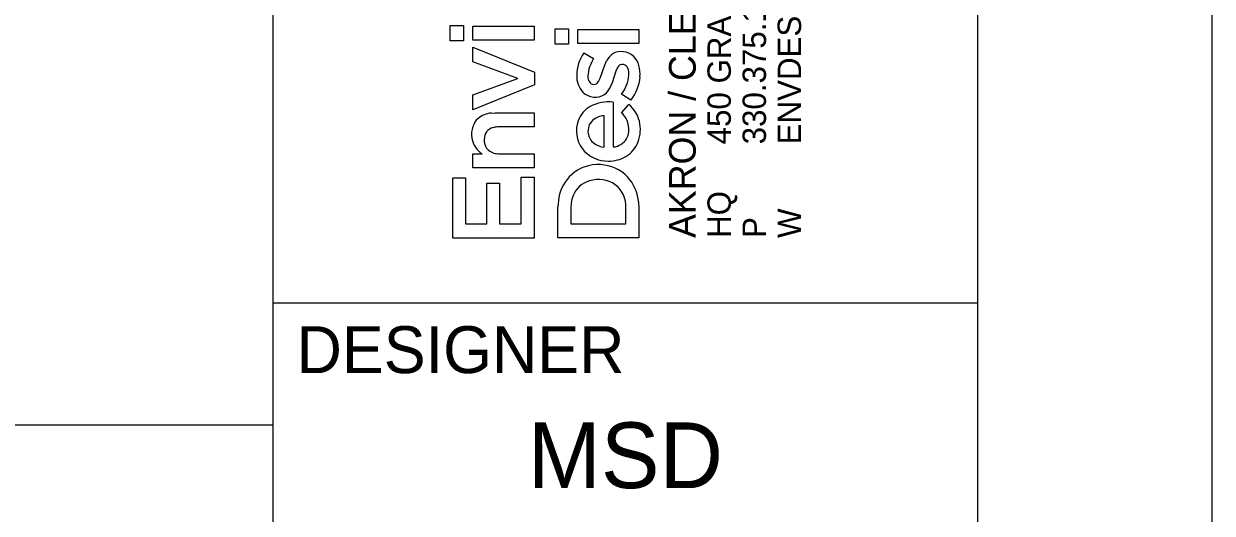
# Model space of a CAD drawing. Extents: x -4279 to 34, y -2047 to 22.
# Drawn here: x 31.469 to 34, y 2.552 to 3.594 of the extents above; entities that cross this region are included whole.
import ezdxf

# ---------------------------------------------------------------- set-up
doc = ezdxf.new("R2010")
doc.units = 0
for name, color, linetype in [('SH_Border', 7, 'Continuous'), ('SH_Cut_Line', 7, 'Continuous'), ('SH_Data', 7, 'Continuous'), ('SH_Text', 7, 'Continuous')]:
    doc.layers.add(name, color=color, linetype=linetype)

msp = doc.modelspace()

# ---------------------------------------------------------------- linework, layer by layer
at = {"layer": 'SH_Border'}
for p, q in [((32, 0.5), (32, 21.5)), ((32, 3), (33.5, 3))]:
    msp.add_line(p, q, dxfattribs=at)
msp.add_lwpolyline([(1.5, 21.5), (33.5, 21.5), (33.5, 0.5), (1.5, 0.5)], close=True, dxfattribs=at)
at = {"layer": 'SH_Cut_Line'}
msp.add_lwpolyline([(0, 0), (34, 0), (34, 22), (0, 22)], close=True, dxfattribs=at)
at = {"layer": 'SH_Data'}
for p, q in [((32.3771, 3.5582), (32.3771, 3.5903)), ((32.3771, 3.5903), (32.4054, 3.5903)), ((32.4054, 3.5903), (32.4054, 3.5582)), ((32.4254, 3.5594), (32.4254, 3.5893)), ((32.4254, 3.5893), (32.5557, 3.5893)), ((32.5557, 3.5893), (32.5557, 3.5594)), ((32.6005, 3.5511), (32.6005, 3.5832)), ((32.6005, 3.5832), (32.6289, 3.5832)), ((32.6289, 3.5832), (32.6289, 3.5511)), ((32.6489, 3.5523), (32.6489, 3.5822)), ((32.6489, 3.5822), (32.7792, 3.5822)), ((32.7792, 3.5822), (32.7792, 3.5523)), ((32.4054, 3.5582), (32.3771, 3.5582)), ((32.5557, 3.5594), (32.4254, 3.5594)), ((32.4254, 3.5133), (32.4254, 3.5446)), ((32.4254, 3.5446), (32.5567, 3.4913)), ((32.6289, 3.5511), (32.6005, 3.5511)), ((32.7792, 3.5523), (32.6489, 3.5523)), ((32.6615, 3.5321), (32.6827, 3.5203)), ((32.5212, 3.478), (32.4254, 3.5133)), ((32.6967, 3.4787), (32.7048, 3.5026)), ((32.7048, 3.5026), (32.7104, 3.5153)), ((32.7298, 3.4933), (32.7221, 3.4688)), ((32.7334, 3.501), (32.7298, 3.4933)), ((32.4254, 3.4429), (32.5212, 3.478)), ((32.5567, 3.4913), (32.5567, 3.4644)), ((32.693, 3.4712), (32.6967, 3.4787)), ((32.7221, 3.4688), (32.7182, 3.4592)), ((32.5567, 3.4644), (32.4254, 3.4109)), ((32.4254, 3.4109), (32.4254, 3.4429)), ((32.7621, 3.4314), (32.742, 3.4447)), ((32.7245, 3.4275), (32.7246, 3.3319)), ((32.7423, 3.4046), (32.7577, 3.422)), ((32.4644, 3.404), (32.4729, 3.4044)), ((32.4729, 3.4044), (32.5557, 3.4044)), ((32.5557, 3.4044), (32.5557, 3.3746)), ((32.7049, 3.3318), (32.7049, 3.3983)), ((32.5557, 3.3746), (32.4814, 3.3746)), ((32.4254, 3.2875), (32.4254, 3.3173)), ((32.4254, 3.3173), (32.4455, 3.3173)), ((32.4822, 3.3173), (32.5557, 3.3173)), ((32.5557, 3.3173), (32.5557, 3.2876)), ((32.7036, 3.3317), (32.7049, 3.3318)), ((32.383, 3.1379), (32.383, 3.266)), ((32.383, 3.266), (32.4101, 3.266)), ((32.4101, 3.266), (32.4101, 3.1683)), ((32.5557, 3.2876), (32.4254, 3.2875)), ((32.5286, 3.1683), (32.5286, 3.2672)), ((32.5286, 3.2672), (32.5557, 3.2672)), ((32.5557, 3.2672), (32.5557, 3.1379)), ((32.455, 3.1683), (32.455, 3.2549)), ((32.455, 3.2549), (32.4822, 3.2549)), ((32.4822, 3.2549), (32.4822, 3.1683)), ((32.7785, 3.215), (32.7792, 3.2021)), ((32.6064, 3.138), (32.6064, 3.204)), ((32.6347, 3.2118), (32.6341, 3.2023)), ((32.6341, 3.2023), (32.6341, 3.1684)), ((32.7515, 3.1683), (32.7515, 3.2024)), ((32.7792, 3.2021), (32.7792, 3.138)), ((32.4101, 3.1683), (32.455, 3.1683)), ((32.4822, 3.1683), (32.5286, 3.1683)), ((32.6341, 3.1684), (32.7515, 3.1683)), ((32.5557, 3.1379), (32.383, 3.1379)), ((32.7792, 3.138), (32.6064, 3.138))]:
    msp.add_line(p, q, dxfattribs=at)
for points in [[(32.3771, 3.5582), (32.3771, 3.5903), (32.4054, 3.5903), (32.4054, 3.5582)], [(32.4254, 3.5594), (32.4254, 3.5893), (32.5557, 3.5893), (32.5557, 3.5594)], [(32.6005, 3.5511), (32.6005, 3.5832), (32.6289, 3.5832), (32.6289, 3.5511)], [(32.6489, 3.5523), (32.6489, 3.5822), (32.7792, 3.5822), (32.7792, 3.5523)], [(32.4254, 3.4109), (32.4254, 3.4429), (32.5212, 3.478), (32.4254, 3.5133), (32.4254, 3.5446), (32.5567, 3.4913), (32.5567, 3.4644)], [(32.383, 3.1379), (32.383, 3.266), (32.4101, 3.266), (32.4101, 3.1683), (32.455, 3.1683), (32.455, 3.2549), (32.4822, 3.2549), (32.4822, 3.1683), (32.5286, 3.1683), (32.5286, 3.2672), (32.5557, 3.2672), (32.5557, 3.1379)]]:
    msp.add_lwpolyline(points, close=True, dxfattribs=at)
for points in [[(32.6615, 3.5321), (32.6827, 3.5203)], [(32.693, 3.4712), (32.6967, 3.4787), (32.7048, 3.5026), (32.7104, 3.5153)], [(32.7334, 3.501), (32.7298, 3.4933), (32.7221, 3.4688), (32.7182, 3.4592)], [(32.7621, 3.4314), (32.742, 3.4447)], [(32.7245, 3.4275), (32.7246, 3.3319)], [(32.7423, 3.4046), (32.7577, 3.422)], [(32.4644, 3.404), (32.4729, 3.4044), (32.5557, 3.4044), (32.5557, 3.3746), (32.4814, 3.3746)], [(32.7036, 3.3317), (32.7049, 3.3318), (32.7049, 3.3983)], [(32.4254, 3.2875), (32.4254, 3.3173), (32.4455, 3.3173)], [(32.4822, 3.3173), (32.5557, 3.3173), (32.5557, 3.2876), (32.4254, 3.2875)], [(32.7785, 3.215), (32.7792, 3.2021), (32.7792, 3.138), (32.6064, 3.138)], [(32.6064, 3.138), (32.6064, 3.204)], [(32.6347, 3.2118), (32.6341, 3.2023), (32.6341, 3.1684), (32.7515, 3.1683), (32.7515, 3.2024)]]:
    msp.add_lwpolyline(points, dxfattribs=at)
for centre, radius, start, end in [((32.7364, 3.4826), 0.0897, 146.531, 178.7571), ((32.7364, 3.4826), 0.0897, 146.531, 178.7571), ((32.7452, 3.4789), 0.0749, 146.5112, 176.9101), ((32.7452, 3.4789), 0.0749, 146.5112, 176.9101), ((32.7466, 3.4971), 0.0405, 125.5118, 153.4159), ((32.7466, 3.4971), 0.0405, 125.5118, 153.4159), ((32.7406, 3.5026), 0.0326, 80.1719, 122.5197), ((32.7406, 3.5026), 0.0326, 80.1719, 122.5197), ((32.7428, 3.4982), 0.0367, 47.7934, 84.6892), ((32.7428, 3.4982), 0.0367, 47.7934, 84.6892), ((32.7379, 3.4946), 0.0427, 14.9966, 46.2063), ((32.7379, 3.4946), 0.0427, 14.9966, 46.2063), ((32.7438, 3.4963), 0.0114, 76.6609, 155.7053), ((32.7438, 3.4963), 0.0114, 76.6609, 155.7053), ((32.744, 3.4951), 0.0126, 21.5098, 78.5262), ((32.744, 3.4951), 0.0126, 21.5098, 78.5262), ((32.7259, 3.4877), 0.0321, 354.5726, 22.068), ((32.7259, 3.4877), 0.0321, 354.5726, 22.068), ((32.7104, 3.4867), 0.0712, 355.8306, 15.3914), ((32.7104, 3.4867), 0.0712, 355.8306, 15.3914), ((32.6967, 3.4824), 0.0501, 177.5366, 222.7932), ((32.6967, 3.4824), 0.0501, 177.5366, 222.7932), ((32.6931, 3.4823), 0.0228, 178.4747, 211.0868), ((32.6931, 3.4823), 0.0228, 178.4747, 211.0868), ((32.6833, 3.4767), 0.0115, 212.2368, 268.3777), ((32.6833, 3.4767), 0.0115, 212.2368, 268.3777), ((32.6834, 3.4759), 0.0107, 267.716, 333.7337), ((32.6834, 3.4759), 0.0107, 267.716, 333.7337), ((32.6825, 3.4915), 0.0757, 321.811, 354.7969), ((32.6825, 3.4915), 0.0757, 321.811, 354.7969), ((32.6895, 3.4882), 0.0922, 321.9777, 355.8738), ((32.6895, 3.4882), 0.0922, 321.9777, 355.8738), ((32.686, 3.4753), 0.0375, 225.9854, 302.4797), ((32.686, 3.4753), 0.0375, 225.9854, 302.4797), ((32.681, 3.4758), 0.0408, 308.0877, 335.9874), ((32.681, 3.4758), 0.0408, 308.0877, 335.9874), ((32.7024, 3.3691), 0.0558, 118.8308, 160.6244), ((32.7024, 3.3691), 0.0558, 118.8308, 160.6244), ((32.7152, 3.3441), 0.0838, 83.615, 118.2876), ((32.7152, 3.3441), 0.0838, 83.615, 118.2876), ((32.7174, 3.3717), 0.0644, 13.5336, 51.3615), ((32.7174, 3.3717), 0.0644, 13.5336, 51.3615), ((32.4635, 3.3626), 0.0402, 132.2219, 161.6818), ((32.4635, 3.3626), 0.0402, 132.2219, 161.6818), ((32.4687, 3.3543), 0.0499, 94.9696, 130.2225), ((32.4687, 3.3543), 0.0499, 94.9696, 130.2225), ((32.7079, 3.3561), 0.0424, 94.008, 130.8817), ((32.7079, 3.3561), 0.0424, 94.008, 130.8817), ((32.7038, 3.3656), 0.0549, 19.0357, 45.4406), ((32.7038, 3.3656), 0.0549, 19.0357, 45.4406), ((32.4787, 3.3582), 0.056, 162.2736, 187.7919), ((32.4787, 3.3582), 0.056, 162.2736, 187.7919), ((32.4748, 3.3487), 0.025, 103.6865, 182.2187), ((32.4748, 3.3487), 0.025, 103.6865, 182.2187), ((32.4811, 3.3286), 0.046, 89.6049, 105.3284), ((32.4811, 3.3286), 0.046, 89.6049, 105.3284), ((32.7104, 3.3661), 0.0644, 160.5201, 215.7831), ((32.7104, 3.3661), 0.0644, 160.5201, 215.7831), ((32.7017, 3.365), 0.0311, 175.0013, 223.283), ((32.7017, 3.365), 0.0311, 175.0013, 223.283), ((32.7005, 3.3663), 0.0298, 132.9851, 177.179), ((32.7005, 3.3663), 0.0298, 132.9851, 177.179), ((32.7107, 3.3697), 0.047, 344.6059, 17.007), ((32.7107, 3.3697), 0.047, 344.6059, 17.007), ((32.7064, 3.3692), 0.0758, 339.3542, 13.3785), ((32.7064, 3.3692), 0.0758, 339.3542, 13.3785), ((32.4703, 3.358), 0.0476, 188.962, 238.7037), ((32.4703, 3.358), 0.0476, 188.962, 238.7037), ((32.4773, 3.3456), 0.0276, 175.5854, 255.1439), ((32.4773, 3.3456), 0.0276, 175.5854, 255.1439), ((32.7089, 3.3736), 0.0423, 225.0619, 262.7974), ((32.7089, 3.3736), 0.0423, 225.0619, 262.7974), ((32.7224, 3.3671), 0.035, 288.0077, 343.5508), ((32.7224, 3.3671), 0.035, 288.0077, 343.5508), ((32.7189, 3.3652), 0.0626, 300.9427, 338.7323), ((32.7189, 3.3652), 0.0626, 300.9427, 338.7323), ((32.4818, 3.3595), 0.0422, 254.0916, 270.5284), ((32.4818, 3.3595), 0.0422, 254.0916, 270.5284), ((32.7125, 3.3705), 0.0687, 217.7452, 271.6543), ((32.7125, 3.3705), 0.0687, 217.7452, 271.6543), ((32.7247, 3.3522), 0.0202, 269.7003, 294.8711), ((32.7247, 3.3522), 0.0202, 269.7003, 294.8711), ((32.6923, 3.2079), 0.0864, 81.194, 125.9984), ((32.6923, 3.2079), 0.0864, 81.194, 125.9984), ((32.6946, 3.2113), 0.0827, 37.8521, 82.402), ((32.6946, 3.2113), 0.0827, 37.8521, 82.402), ((32.7155, 3.3724), 0.0706, 269.2048, 300.3341), ((32.7155, 3.3724), 0.0706, 269.2048, 300.3341), ((32.6939, 3.2089), 0.0865, 127.2362, 165.148), ((32.6939, 3.2089), 0.0865, 127.2362, 165.148), ((32.6889, 3.2078), 0.054, 106.1881, 157.3861), ((32.6889, 3.2078), 0.054, 106.1881, 157.3861), ((32.6928, 3.1986), 0.0639, 55.6727, 107.2093), ((32.6928, 3.1986), 0.0639, 55.6727, 107.2093), ((32.6929, 3.205), 0.0587, 357.4662, 52.2665), ((32.6929, 3.205), 0.0587, 357.4662, 52.2665), ((32.6859, 3.2057), 0.0931, 5.7333, 37.304), ((32.6859, 3.2057), 0.0931, 5.7333, 37.304), ((32.7143, 3.2028), 0.1078, 164.7861, 179.3704), ((32.7143, 3.2028), 0.1078, 164.7861, 179.3704), ((32.6983, 3.2039), 0.0641, 157.3571, 172.9275), ((32.6983, 3.2039), 0.0641, 157.3571, 172.9275)]:
    msp.add_arc(centre, radius, start, end, dxfattribs=at)
at = {"layer": 'SH_Text'}
msp.add_line((25.1966, 2.74), (32, 2.74), dxfattribs=at)

# ---------------------------------------------------------------- texts
at = {"layer": 'SH_Data'}
for s, height, p in [('450 GRANT ST., AKRON, OH  44311', 0.049846, (32.9749, 3.3374)), ('AKRON / CLEVELAND / COLUMBUS', 0.056969, (32.9001, 3.138)), ('ENVDESIGNGROUP.COM', 0.049846, (33.1244, 3.3374)), ('330.375.1390', 0.049846, (33.0497, 3.3374)), ('HQ ', 0.04985, (32.9749, 3.138)), ('W', 0.0498, (33.1244, 3.138)), ('P', 0.0498, (33.0497, 3.138))]:
    msp.add_text(s, height=height, rotation=90, dxfattribs=at).set_placement(p)
for s, height, p in [('DESIGNER', 0.1, (32.05, 2.85)), ('MSD', 0.14, (32.5422, 2.605))]:
    msp.add_text(s, height=height, dxfattribs=at).set_placement(p)

doc.saveas('drawing.dxf')
